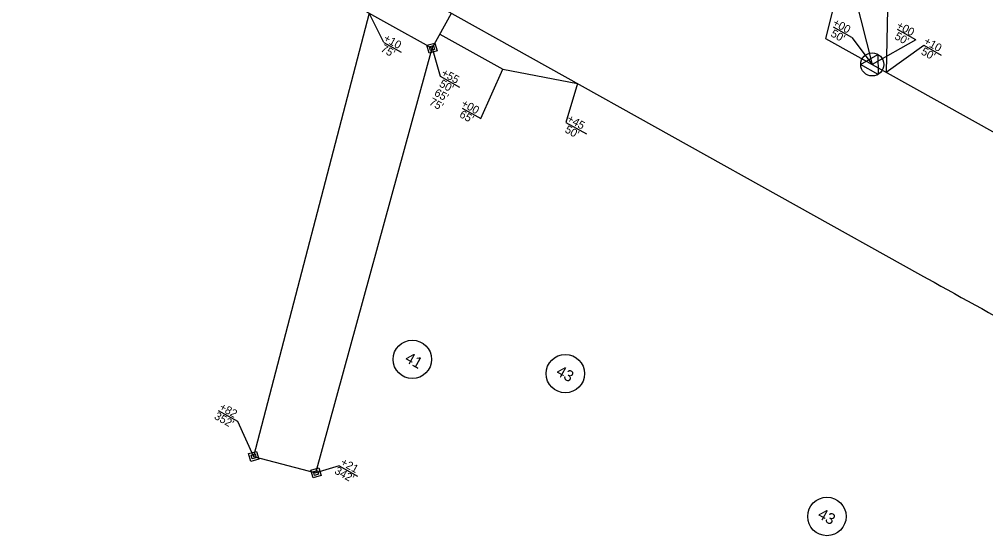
# Model space of a CAD drawing. Extents: x 1762160 to 1765875, y 710174 to 712931.
# Drawn here: x 1764564 to 1765167, y 710437 to 710760 of the extents above; entities that cross this region are included whole.
import ezdxf

# ---------------------------------------------------------------- set-up
doc = ezdxf.new("R2010")
doc.units = 0
for name, color, linetype in [('Exist Building Foundations', 7, 'Continuous'), ('Exist Other Culture Area Outline', 7, 'Continuous'), ('Exist Other Culture Fence Line', 7, 'Continuous'), ('Exist Other Culture Located Object CELL', 7, 'Continuous'), ('Exist Other Culture Sign CELL', 7, 'Continuous'), ('Exist Roads Curbs', 7, 'Continuous'), ('Exist Roads EOP Other', 7, 'Continuous'), ('Exist Roads Soil', 7, 'Continuous'), ('Exist Structure Minor Head and End Wall', 7, 'Continuous'), ('Exist Utilities Other Pole CELL', 7, 'Continuous'), ('Exist Utilities Other Pole With Base CELL', 7, 'Continuous'), ('Exist Vegetation Tree CELL', 7, 'Continuous'), ('Exist Vegetation Woods Line', 7, 'Continuous')]:
    doc.layers.add(name, color=color, linetype=linetype)

msp = doc.modelspace()

# ---------------------------------------------------------------- linework, layer by layer
at = {"layer": 'Exist Building Foundations'}
for p, q in [((1764782.11, 710763.99), (1764710.03, 710487.01)), ((1764748.96, 710476.74), (1764821.41, 710742.06)), ((1764710.03, 710487.01), (1764748.96, 710476.74))]:
    msp.add_line(p, q, dxfattribs=at)
at = {"layer": 'Exist Other Culture Area Outline'}
msp.add_line((1765079.51, 710797.73), (1765096.26, 710731.86), dxfattribs=at)
at = {"layer": 'Exist Other Culture Fence Line'}
for p, q in [((1764791.34, 710745.57), (1764782.11, 710763.99)), ((1764791.34, 710745.57), (1764802.16, 710739.55)), ((1764687.81, 710515.77), (1764700.03, 710508.96)), ((1764700.03, 710508.96), (1764710.03, 710487.01)), ((1764763.36, 710481.15), (1764748.96, 710476.74)), ((1764763.36, 710481.15), (1764774.86, 710474.74))]:
    msp.add_line(p, q, dxfattribs=at)
at = {"layer": 'Exist Other Culture Located Object CELL'}
for p, q in [((1765105, 710726.99), (1765128.39, 710743.87)), ((1765128.39, 710743.87), (1765139.42, 710737.72)), ((1764851.84, 710698.11), (1764865.58, 710728.87)), ((1764912.18, 710720.05), (1764904.91, 710695.68)), ((1764840.17, 710704.61), (1764851.84, 710698.11)), ((1764904.91, 710695.68), (1764917.83, 710688.49))]:
    msp.add_line(p, q, dxfattribs=at)
at = {"layer": 'Exist Other Culture Sign CELL'}
for p, q in [((1764821.41, 710742.06), (1764826.43, 710724.45)), ((1764826.43, 710724.45), (1764838.59, 710717.67))]:
    msp.add_line(p, q, dxfattribs=at)
at = {"layer": 'Exist Roads Curbs'}
for p, q in [((1764821.41, 710742.06), (1764821.41, 710742.06)), ((1765096.26, 710731.86), (1765096.26, 710731.86)), ((1764710.03, 710487.01), (1764710.03, 710487.01)), ((1764748.96, 710476.74), (1764748.96, 710476.74))]:
    msp.add_line(p, q, dxfattribs=at)
msp.add_lwpolyline([(1765089.05, 710731.76), (1765099.77, 710738.15), (1765099.97, 710725.68)], close=True, dxfattribs=at)
msp.add_circle((1765096.26, 710731.86), 7.2, dxfattribs=at)
at = {"layer": 'Exist Roads EOP Other'}
for p, q in [((1765105.88, 710766.35), (1765105, 710726.99)), ((1764826.28, 710750.8), (1764865.58, 710728.87)), ((1764865.58, 710728.87), (1764912.18, 710720.05))]:
    msp.add_line(p, q, dxfattribs=at)
at = {"layer": 'Exist Roads Soil'}
for p, q in [((1764624.92, 710851.68), (1764821.41, 710742.06)), ((1764821.41, 710742.06), (1764833.59, 710763.9))]:
    msp.add_line(p, q, dxfattribs=at)
at = {"layer": 'Exist Structure Minor Head and End Wall'}
for points in [[(1764823.16, 710745.21), (1764824.55, 710740.31), (1764819.66, 710738.92), (1764818.26, 710743.82)], [(1764822.28, 710743.64), (1764822.98, 710741.19), (1764820.53, 710740.49), (1764819.84, 710742.94)], [(1764706.89, 710488.76), (1764711.79, 710490.15), (1764713.18, 710485.26), (1764708.28, 710483.86)], [(1764708.46, 710487.88), (1764710.91, 710488.58), (1764711.61, 710486.13), (1764709.16, 710485.44)], [(1764745.82, 710478.49), (1764750.72, 710479.89), (1764752.11, 710474.99), (1764747.21, 710473.59)], [(1764747.39, 710477.62), (1764749.84, 710478.31), (1764750.54, 710475.86), (1764748.09, 710475.17)]]:
    msp.add_lwpolyline(points, close=True, dxfattribs=at)
at = {"layer": 'Exist Utilities Other Pole CELL'}
for p, q in [((1765083.6, 710748.66), (1765072.05, 710755.09)), ((1765123.41, 710747.3), (1765112.01, 710753.65)), ((1765123.41, 710747.3), (1765096.26, 710731.86))]:
    msp.add_line(p, q, dxfattribs=at)
msp.add_lwpolyline([(1765083.6, 710748.66), (1765096.26, 710731.86)], dxfattribs=at)
at = {"layer": 'Exist Utilities Other Pole With Base CELL'}
for p, q in [((1765130.99, 711003.66), (1765067.11, 710748.13)), ((1764563.72, 710914.45), (1765126.44, 710600.52)), ((1765067.11, 710748.13), (1765175.16, 710687.85))]:
    msp.add_line(p, q, dxfattribs=at)
msp.add_arc((1770022.75, 719377.11), 10050, 240.843598, 241.286353, dxfattribs=at)
at = {"layer": 'Exist Vegetation Tree CELL'}
for centre in [(1764809.12, 710547.63), (1764904.62, 710538.73), (1765067.98, 710449.5)]:
    msp.add_circle(centre, 12, dxfattribs=at)

# ---------------------------------------------------------------- texts
at = {"layer": 'Exist Other Culture Fence Line'}
for s, p in [('+10', (1764790.62, 710746.81)), ("75'", (1764788.93, 710740.31)), ('+82', (1764688.12, 710516.45)), ("352'", (1764684.99, 710510.75)), ("342'", (1764760.07, 710476.62)), ('+21', (1764763.83, 710481.96))]:
    msp.add_text(s, height=5, rotation=330.89322, dxfattribs=at).set_placement(p)
at = {"layer": 'Exist Other Culture Located Object CELL'}
for s, p in [('+10', (1765128, 710745.01)), ("50'", (1765126.31, 710738.51)), ('+00', (1764839.21, 710706.07)), ("65'", (1764838.04, 710699.28)), ('+45', (1764905.14, 710696.53)), ("50'", (1764903.88, 710689.78))]:
    msp.add_text(s, height=5, rotation=330.88857, dxfattribs=at).set_placement(p)
at = {"layer": 'Exist Other Culture Sign CELL'}
for s, p in [('+55', (1764826.75, 710725.14)), ("50'", (1764825.5, 710718.39)), ("65'", (1764822.33, 710712.72)), ("75'", (1764819.17, 710707.04))]:
    msp.add_text(s, height=5, rotation=330.89322, dxfattribs=at).set_placement(p)
at = {"layer": 'Exist Utilities Other Pole CELL'}
for s, p in [('+00', (1765071.08, 710756.52)), ('+00', (1765110.96, 710754.84)), ("50'", (1765069.91, 710749.73)), ("50'", (1765109.8, 710748.05))]:
    msp.add_text(s, height=5, rotation=330.88857, dxfattribs=at).set_placement(p)
at = {"layer": 'Exist Vegetation Woods Line'}
for s, p in [('41', (1764803.9, 710546.5)), ('43', (1764898.33, 710538.2)), ('43', (1765061.68, 710448.96))]:
    msp.add_text(s, height=7, rotation=330.88857, dxfattribs=at).set_placement(p)

doc.saveas('drawing.dxf')
